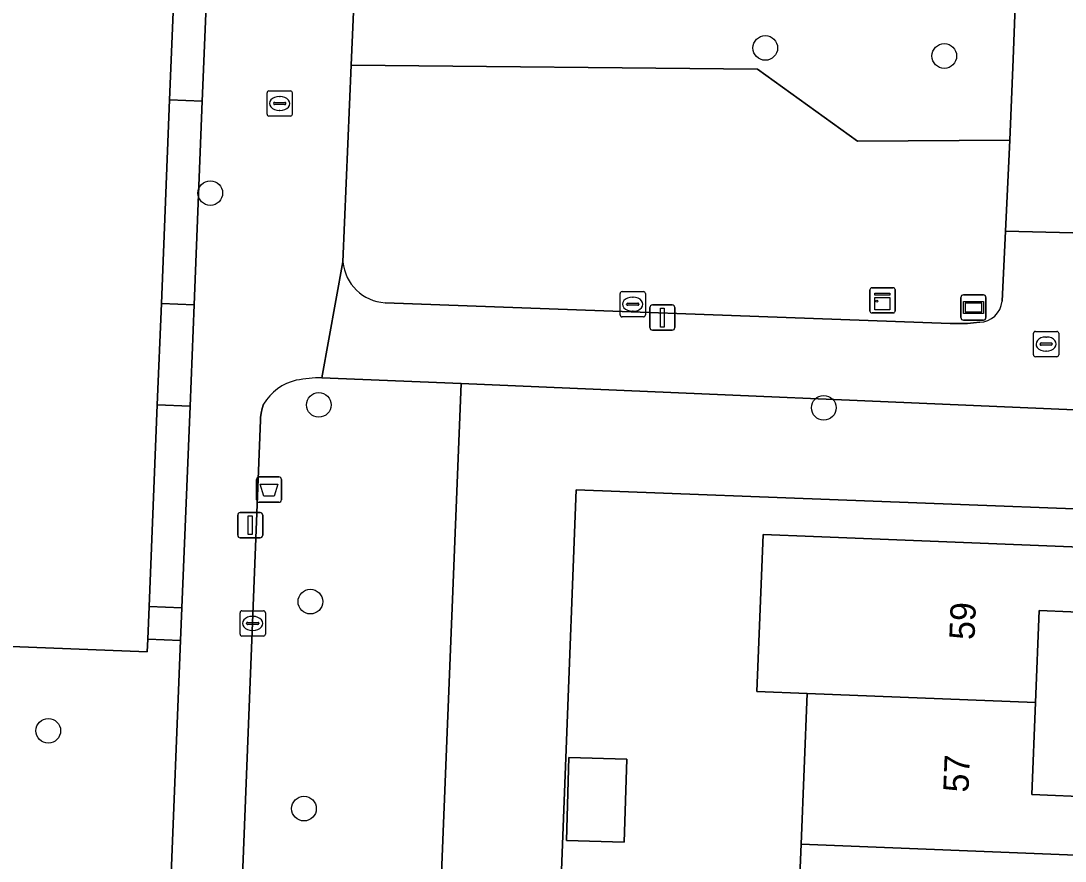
# Model space of a CAD drawing. Extents: x 160786 to 161429, y 386828 to 387485.
# Drawn here: x 161125.82 to 161167.19, y 387264.64 to 387297.93 of the extents above; entities that cross this region are included whole.
import ezdxf

# ---------------------------------------------------------------- set-up
doc = ezdxf.new("R2010")
doc.units = 0
for name, color, linetype in [('IMGEO_Afvalbak', 7, 'Continuous'), ('IMGEO_Boom', 7, 'Continuous'), ('IMGEO_Brandkraan', 7, 'Continuous'), ('IMGEO_Erf', 7, 'Continuous'), ('IMGEO_Groenvoorziening', 7, 'Continuous'), ('IMGEO_Haag', 7, 'Continuous'), ('IMGEO_Kast', 7, 'Continuous'), ('IMGEO_Kolk', 7, 'Continuous'), ('IMGEO_Lichtmast', 7, 'Continuous'), ('IMGEO_Pand', 7, 'Continuous'), ('IMGEO_Pand_nummerreeks', 7, 'Continuous'), ('IMGEO_Straatnaambord', 7, 'Continuous'), ('IMGEO_Voetpad_open', 7, 'Continuous')]:
    doc.layers.add(name, color=color, linetype=linetype)

msp = doc.modelspace()

# ---------------------------------------------------------------- linework, layer by layer
at = {"layer": 'IMGEO_Afvalbak'}
for p, q in [((161135.253, 387279.862), (161136.043, 387279.862)), ((161136.043, 387279.862), (161135.253, 387279.862)), ((161135.153, 387278.962), (161135.153, 387279.762)), ((161135.153, 387279.762), (161135.153, 387278.962)), ((161136.143, 387279.762), (161136.143, 387278.962)), ((161136.143, 387278.962), (161136.143, 387279.762)), ((161136.043, 387278.862), (161135.253, 387278.862)), ((161135.253, 387278.862), (161136.043, 387278.862))]:
    msp.add_line(p, q, dxfattribs=at)
msp.add_lwpolyline([(161135.296, 387279.576), (161136, 387279.576), (161135.851, 387279.106), (161135.445, 387279.106), (161135.296, 387279.576)], dxfattribs=at)
for centre, start, end in [((161135.253, 387279.762), 90, 180), ((161135.253, 387279.762), 90, 180), ((161136.043, 387279.762), 0, 90), ((161136.043, 387279.762), 360, 90), ((161135.253, 387278.962), 180, 270), ((161135.253, 387278.962), 180, 270), ((161136.043, 387278.962), 270, 0), ((161136.043, 387278.962), 270, 0)]:
    msp.add_arc(centre, 0.1, start, end, dxfattribs=at)
at = {"layer": 'IMGEO_Boom'}
for centre in [(161155.308, 387296.861), (161162.4, 387296.541), (161133.321, 387291.109), (161137.619, 387282.717), (161157.626, 387282.603), (161137.288, 387274.923), (161126.901, 387269.805), (161137.032, 387266.723)]:
    msp.add_circle(centre, 0.489, dxfattribs=at)
at = {"layer": 'IMGEO_Brandkraan'}
for p, q in [((161166.01, 387285.627), (161166.862, 387285.627)), ((161165.935, 387284.701), (161165.935, 387285.553)), ((161166.237, 387285.17), (161166.635, 387285.17)), ((161166.423, 387285.407), (161166.448, 387285.407)), ((161166.936, 387285.553), (161166.936, 387284.701)), ((161166.194, 387285.121), (161166.194, 387285.133)), ((161166.632, 387285.084), (161166.234, 387285.084)), ((161166.446, 387284.847), (161166.421, 387284.847)), ((161166.678, 387285.133), (161166.678, 387285.121)), ((161166.862, 387284.627), (161166.01, 387284.627))]:
    msp.add_line(p, q, dxfattribs=at)
for points in [[(161166.01, 387285.627), (161166.862, 387285.627)], [(161165.935, 387284.701), (161165.935, 387285.553)], [(161166.936, 387285.553), (161166.936, 387284.701)], [(161166.862, 387284.627), (161166.01, 387284.627)]]:
    msp.add_lwpolyline(points, dxfattribs=at)
for centre, radius, start, end in [((161166.012, 387285.551), 0.0765, 91.552, 178.448), ((161166.012, 387285.551), 0.0765, 91.552, 178.448), ((161166.86, 387285.551), 0.0765, 1.552, 88.448), ((161166.86, 387285.551), 0.0765, 1.552, 88.448), ((161166.234, 387285.13), 0.0403, 85.8775, 175.7526), ((161166.639, 387285.132), 0.0386, 1.7309, 96.639), ((161166.231, 387285.12), 0.0366, 178.938, 274.7102), ((161166.635, 387285.127), 0.043, 264.8664, 352.4533), ((161166.012, 387284.703), 0.0765, 181.552, 268.448), ((161166.012, 387284.703), 0.0765, 181.552, 268.448), ((161166.86, 387284.703), 0.0765, 271.552, 358.448), ((161166.86, 387284.703), 0.0765, 271.552, 358.448)]:
    msp.add_arc(centre, radius, start, end, dxfattribs=at)
for centre, major_axis, ratio, start_param, end_param in [((161166.422, 387285.127), (-0.387, 0.002), 0.722429, 4.712389, 7.853982), ((161166.447, 387285.127), (-0.39, 0.002), 0.717154, 1.570796, 4.712389)]:
    msp.add_ellipse(centre, major_axis=major_axis, ratio=ratio, start_param=start_param, end_param=end_param, dxfattribs=at)
at = {"layer": 'IMGEO_Erf'}
for points in [[(161118.71, 387273.409), (161130.826, 387272.934), (161130.846, 387273.44), (161130.898, 387274.729), (161131.22, 387282.723), (161131.382, 387286.74), (161131.706, 387294.803), (161131.872, 387298.919), (161132.197, 387307.013), (161132.363, 387311.119), (161132.69, 387319.253), (161132.836, 387322.88), (161133.163, 387331.014), (161133.328, 387335.1), (161133.655, 387343.234), (161133.705, 387344.483), (161133.977, 387351.235), (161125.69, 387351.675)], [(161156.486, 387259.313), (161156.726, 387265.307), (161156.965, 387271.285), (161154.974, 387271.365), (161155.223, 387277.582), (161157.214, 387277.502), (161168.771, 387277.039), (161168.668, 387274.465), (161166.166, 387274.565), (161166.02, 387270.922), (161165.874, 387267.279), (161168.363, 387267.179), (161168.27, 387264.845), (161168.177, 387262.51)]]:
    msp.add_lwpolyline(points, dxfattribs=at)
for points in [[(161169.695, 387236.621), (161169.709, 387236.985), (161170.226, 387250), (161171.292, 387276.874), (161171.353, 387278.449), (161147.813, 387279.35), (161146.59, 387247.494), (161144.751, 387247.564), (161143.809, 387246.052), (161142.905, 387223.679), (161145.53, 387223.573), (161145.284, 387217.483), (161143.51, 387217.555), (161143.326, 387213), (161145.236, 387212.923), (161144.626, 387197.819), (161152.342, 387197.507), (161162.811, 387197.084), (161168.116, 387196.87), (161168.129, 387197.191), (161168.175, 387198.326)], [(161147.429, 387265.462), (161147.528, 387268.745), (161149.818, 387268.675), (161149.719, 387265.392)]]:
    msp.add_lwpolyline(points, close=True, dxfattribs=at)
at = {"layer": 'IMGEO_Groenvoorziening'}
for points in [[(161165.127, 387296.415), (161165.215, 387298.514), (161160.443, 387298.696), (161151.391, 387299.041), (161143.553, 387299.341), (161139.046, 387299.512), (161138.908, 387296.177), (161155.006, 387296.014), (161158.958, 387293.171), (161164.993, 387293.208)], [(161133.005, 387294.751), (161131.706, 387294.803), (161131.382, 387286.74), (161132.681, 387286.688)], [(161132.519, 387282.671), (161131.22, 387282.723), (161130.898, 387274.729), (161132.198, 387274.677)]]:
    msp.add_lwpolyline(points, close=True, dxfattribs=at)
for points in [[(161164.829, 387289.6), (161164.993, 387293.208), (161158.958, 387293.171), (161155.006, 387296.014), (161138.908, 387296.177), (161138.578, 387288.383)], [(161164.69, 387286.821), (161164.829, 387289.6)], [(161140.247, 387286.767), (161162.637, 387285.947), (161163.314, 387285.947), (161163.563, 387285.964), (161163.803, 387285.99)], [(161143.258, 387283.56), (161137.745, 387283.796)], [(161169.71, 387282.428), (161143.258, 387283.56), (161141.91, 387250), (161139.825, 387198.117), (161139.779, 387196.96), (161145.215, 387196.742), (161162.77, 387196.036), (161162.811, 387197.084), (161152.342, 387197.507), (161144.626, 387197.819), (161145.236, 387212.923), (161143.326, 387213), (161143.51, 387217.555), (161145.284, 387217.483), (161145.53, 387223.573), (161142.905, 387223.679), (161143.809, 387246.052), (161144.751, 387247.564), (161146.59, 387247.494), (161147.813, 387279.35), (161171.353, 387278.449), (161171.423, 387280.284), (161171.366, 387280.761)], [(161141.91, 387250), (161143.258, 387283.56)], [(161135.431, 387282.75), (161135.375, 387282.575), (161135.335, 387282.396), (161135.31, 387282.213), (161135.304, 387282.111), (161134.046, 387250), (161131.872, 387194.508), (161131.578, 387188.533)], [(161132.146, 387273.388), (161130.846, 387273.44), (161130.826, 387272.934), (161118.71, 387273.409), (161109.694, 387273.762), (161104.756, 387273.893), (161104.419, 387265.337), (161104.372, 387264.144)], [(161131.733, 387263.132), (161132.146, 387273.388)]]:
    msp.add_lwpolyline(points, dxfattribs=at)
for centre, radius, start, end in [((161140.345, 387288.538), 1.774, 185.0156, 266.8331), ((161163.775, 387286.909), 0.92, 271.7735, 354.4926), ((161137.172, 387281.713), 2.027, 102.6102, 149.2292), ((161137.866, 387277.667), 6.13, 91.1319, 100.6804)]:
    msp.add_arc(centre, radius, start, end, dxfattribs=at)
at = {"layer": 'IMGEO_Haag'}
for points in [[(161133.005, 387294.751), (161131.706, 387294.803), (161131.382, 387286.74), (161132.681, 387286.688)], [(161132.519, 387282.671), (161131.22, 387282.723), (161130.898, 387274.729), (161132.198, 387274.677)]]:
    msp.add_lwpolyline(points, close=True, dxfattribs=at)
at = {"layer": 'IMGEO_Kast'}
for p, q in [((161159.454, 387286.435), (161159.454, 387287.276)), ((161159.454, 387287.276), (161159.454, 387286.435)), ((161159.529, 387287.36), (161160.37, 387287.36)), ((161160.37, 387287.36), (161159.529, 387287.36)), ((161160.454, 387287.285), (161160.454, 387286.444)), ((161160.454, 387286.444), (161160.454, 387287.285)), ((161160.379, 387286.36), (161159.538, 387286.36)), ((161159.538, 387286.36), (161160.379, 387286.36))]:
    msp.add_line(p, q, dxfattribs=at)
for points in [[(161159.649, 387287.15), (161160.249, 387287.15), (161160.249, 387287.065), (161159.649, 387287.065), (161159.649, 387287.15)], [(161159.649, 387286.975), (161160.249, 387286.975), (161160.249, 387286.486), (161159.649, 387286.486), (161159.649, 387286.975)]]:
    msp.add_lwpolyline(points, dxfattribs=at)
msp.add_circle((161159.733, 387286.824), 0.0377, dxfattribs=at)
for centre, start, end in [((161159.532, 387287.282), 92.4484, 184.2845), ((161159.532, 387287.282), 92.4484, 184.2845), ((161160.376, 387287.282), 2.4484, 94.2845), ((161160.376, 387287.282), 2.4484, 94.2845), ((161159.532, 387286.438), 182.4484, 274.2845), ((161159.532, 387286.438), 182.4484, 274.2845), ((161160.376, 387286.438), 272.4484, 4.2845), ((161160.376, 387286.438), 272.4484, 4.2845)]:
    msp.add_arc(centre, 0.0779, start, end, dxfattribs=at)
at = {"layer": 'IMGEO_Kolk'}
for p, q in [((161135.57, 387294.233), (161135.57, 387295.085)), ((161135.645, 387295.159), (161136.497, 387295.159)), ((161136.571, 387295.085), (161136.571, 387294.233)), ((161135.829, 387294.653), (161135.829, 387294.665)), ((161135.872, 387294.702), (161136.27, 387294.702)), ((161136.058, 387294.939), (161136.083, 387294.939)), ((161136.313, 387294.665), (161136.313, 387294.653)), ((161136.267, 387294.616), (161135.869, 387294.616)), ((161136.081, 387294.379), (161136.056, 387294.379)), ((161136.497, 387294.159), (161135.645, 387294.159)), ((161149.558, 387286.281), (161149.558, 387287.133)), ((161149.633, 387287.207), (161150.485, 387287.207)), ((161150.046, 387286.987), (161150.071, 387286.987)), ((161150.559, 387287.133), (161150.559, 387286.281)), ((161149.817, 387286.701), (161149.817, 387286.713)), ((161150.255, 387286.664), (161149.857, 387286.664)), ((161149.86, 387286.75), (161150.258, 387286.75)), ((161150.069, 387286.427), (161150.044, 387286.427)), ((161150.301, 387286.713), (161150.301, 387286.701)), ((161150.485, 387286.207), (161149.633, 387286.207)), ((161134.501, 387273.633), (161134.501, 387274.485)), ((161134.576, 387274.559), (161135.428, 387274.559)), ((161135.502, 387274.485), (161135.502, 387273.633)), ((161134.76, 387274.053), (161134.76, 387274.065)), ((161135.198, 387274.016), (161134.8, 387274.016)), ((161134.803, 387274.102), (161135.201, 387274.102)), ((161134.989, 387274.339), (161135.014, 387274.339)), ((161135.244, 387274.065), (161135.244, 387274.053)), ((161135.428, 387273.559), (161134.576, 387273.559)), ((161135.012, 387273.779), (161134.987, 387273.779))]:
    msp.add_line(p, q, dxfattribs=at)
for points in [[(161135.57, 387294.233), (161135.57, 387295.085)], [(161135.645, 387295.159), (161136.497, 387295.159)], [(161136.571, 387295.085), (161136.571, 387294.233)], [(161136.497, 387294.159), (161135.645, 387294.159)], [(161149.558, 387286.281), (161149.558, 387287.133)], [(161149.633, 387287.207), (161150.485, 387287.207)], [(161150.559, 387287.133), (161150.559, 387286.281)], [(161150.485, 387286.207), (161149.633, 387286.207)], [(161134.501, 387273.633), (161134.501, 387274.485)], [(161134.576, 387274.559), (161135.428, 387274.559)], [(161135.502, 387274.485), (161135.502, 387273.633)], [(161135.428, 387273.559), (161134.576, 387273.559)]]:
    msp.add_lwpolyline(points, dxfattribs=at)
for centre, radius, start, end in [((161135.647, 387295.083), 0.0765, 91.552, 178.448), ((161135.647, 387295.083), 0.0765, 91.552, 178.448), ((161136.495, 387295.083), 0.0765, 1.552, 88.448), ((161136.495, 387295.083), 0.0765, 1.552, 88.448), ((161135.869, 387294.662), 0.0403, 85.8775, 175.7526), ((161136.274, 387294.664), 0.0386, 1.7309, 96.639), ((161135.866, 387294.652), 0.0366, 178.938, 274.7102), ((161136.27, 387294.659), 0.043, 264.8664, 352.4533), ((161135.647, 387294.235), 0.0765, 181.552, 268.448), ((161135.647, 387294.235), 0.0765, 181.552, 268.448), ((161136.495, 387294.235), 0.0765, 271.552, 358.448), ((161136.495, 387294.235), 0.0765, 271.552, 358.448), ((161149.635, 387287.131), 0.0765, 91.552, 178.448), ((161149.635, 387287.131), 0.0765, 91.552, 178.448), ((161150.483, 387287.131), 0.0765, 1.552, 88.448), ((161150.483, 387287.131), 0.0765, 1.552, 88.448), ((161149.857, 387286.71), 0.0403, 85.8775, 175.7526), ((161149.854, 387286.7), 0.0366, 178.938, 274.7102), ((161150.258, 387286.707), 0.043, 264.8664, 352.4533), ((161150.262, 387286.712), 0.0386, 1.7309, 96.639), ((161149.635, 387286.283), 0.0765, 181.552, 268.448), ((161149.635, 387286.283), 0.0765, 181.552, 268.448), ((161150.483, 387286.283), 0.0765, 271.552, 358.448), ((161150.483, 387286.283), 0.0765, 271.552, 358.448), ((161134.578, 387274.483), 0.0765, 91.552, 178.448), ((161134.578, 387274.483), 0.0765, 91.552, 178.448), ((161135.426, 387274.483), 0.0765, 1.552, 88.448), ((161135.426, 387274.483), 0.0765, 1.552, 88.448), ((161134.8, 387274.062), 0.0403, 85.8775, 175.7526), ((161134.797, 387274.052), 0.0366, 178.938, 274.7102), ((161135.201, 387274.059), 0.043, 264.8664, 352.4533), ((161135.205, 387274.064), 0.0386, 1.7309, 96.639), ((161134.578, 387273.635), 0.0765, 181.552, 268.448), ((161134.578, 387273.635), 0.0765, 181.552, 268.448), ((161135.426, 387273.635), 0.0765, 271.552, 358.448), ((161135.426, 387273.635), 0.0765, 271.552, 358.448)]:
    msp.add_arc(centre, radius, start, end, dxfattribs=at)
for centre, major_axis, ratio, start_param, end_param in [((161136.057, 387294.659), (-0.387, 0.002), 0.722429, 4.712389, 7.853982), ((161136.082, 387294.659), (-0.39, 0.002), 0.717154, 1.570796, 4.712389), ((161150.045, 387286.707), (-0.387, 0.002), 0.722429, 4.712389, 7.853982), ((161150.07, 387286.707), (-0.39, 0.002), 0.717154, 1.570796, 4.712389), ((161134.988, 387274.059), (-0.387, 0.002), 0.722429, 4.712389, 7.853982), ((161135.013, 387274.059), (-0.39, 0.002), 0.717154, 1.570796, 4.712389)]:
    msp.add_ellipse(centre, major_axis=major_axis, ratio=ratio, start_param=start_param, end_param=end_param, dxfattribs=at)
at = {"layer": 'IMGEO_Lichtmast'}
for p, q in [((161150.735, 387285.778), (161150.735, 387286.578)), ((161150.735, 387286.578), (161150.735, 387285.778)), ((161150.835, 387286.678), (161151.625, 387286.678)), ((161151.625, 387286.678), (161150.835, 387286.678)), ((161151.725, 387286.578), (161151.725, 387285.778)), ((161151.725, 387285.778), (161151.725, 387286.578)), ((161151.625, 387285.678), (161150.835, 387285.678)), ((161150.835, 387285.678), (161151.625, 387285.678)), ((161134.406, 387277.552), (161134.406, 387278.352)), ((161134.406, 387278.352), (161134.406, 387277.552)), ((161134.506, 387278.452), (161135.296, 387278.452)), ((161135.296, 387278.452), (161134.506, 387278.452)), ((161135.396, 387278.352), (161135.396, 387277.552)), ((161135.396, 387277.552), (161135.396, 387278.352)), ((161135.296, 387277.452), (161134.506, 387277.452)), ((161134.506, 387277.452), (161135.296, 387277.452))]:
    msp.add_line(p, q, dxfattribs=at)
for points in [[(161151.155, 387286.553), (161151.305, 387286.553), (161151.305, 387285.803), (161151.155, 387285.803), (161151.155, 387286.553)], [(161134.826, 387278.327), (161134.976, 387278.327), (161134.976, 387277.577), (161134.826, 387277.577), (161134.826, 387278.327)]]:
    msp.add_lwpolyline(points, dxfattribs=at)
for centre, start, end in [((161150.835, 387286.578), 90, 180), ((161150.835, 387286.578), 90, 180), ((161151.625, 387286.578), 0, 90), ((161151.625, 387286.578), 360, 90), ((161150.835, 387285.778), 180, 270), ((161150.835, 387285.778), 180, 270), ((161151.625, 387285.778), 270, 0), ((161151.625, 387285.778), 270, 0), ((161134.506, 387278.352), 90, 180), ((161134.506, 387278.352), 90, 180), ((161135.296, 387278.352), 0, 90), ((161135.296, 387278.352), 360, 90), ((161134.506, 387277.552), 180, 270), ((161134.506, 387277.552), 180, 270), ((161135.296, 387277.552), 270, 0), ((161135.296, 387277.552), 270, 0)]:
    msp.add_arc(centre, 0.1, start, end, dxfattribs=at)
at = {"layer": 'IMGEO_Pand'}
for points in [[(161166.166, 387274.565), (161168.668, 387274.465), (161168.771, 387277.039), (161157.214, 387277.502), (161155.223, 387277.582), (161154.974, 387271.365), (161156.965, 387271.285), (161166.02, 387270.922)], [(161168.27, 387264.845), (161168.363, 387267.179), (161165.874, 387267.279), (161166.02, 387270.922), (161156.965, 387271.285), (161156.726, 387265.307)], [(161147.429, 387265.462), (161149.719, 387265.392), (161149.818, 387268.675), (161147.528, 387268.745)], [(161165.498, 387258.952), (161165.644, 387262.611), (161168.177, 387262.51), (161168.27, 387264.845), (161156.726, 387265.307), (161156.486, 387259.313)]]:
    msp.add_lwpolyline(points, close=True, dxfattribs=at)
at = {"layer": 'IMGEO_Straatnaambord'}
for p, q in [((161163.059, 387286.176), (161163.059, 387286.976)), ((161163.059, 387286.976), (161163.059, 387286.176)), ((161163.159, 387287.076), (161163.949, 387287.076)), ((161163.949, 387287.076), (161163.159, 387287.076)), ((161164.049, 387286.976), (161164.049, 387286.176)), ((161164.049, 387286.176), (161164.049, 387286.976)), ((161163.949, 387286.076), (161163.159, 387286.076)), ((161163.159, 387286.076), (161163.949, 387286.076))]:
    msp.add_line(p, q, dxfattribs=at)
for points in [[(161163.16, 387286.808), (161163.948, 387286.808), (161163.948, 387286.344), (161163.16, 387286.344), (161163.16, 387286.808)], [(161163.225, 387286.743), (161163.225, 387286.409), (161163.883, 387286.409), (161163.883, 387286.743), (161163.225, 387286.743)]]:
    msp.add_lwpolyline(points, dxfattribs=at)
for centre, start, end in [((161163.159, 387286.976), 90, 180), ((161163.159, 387286.976), 90, 180), ((161163.949, 387286.976), 0, 90), ((161163.949, 387286.976), 360, 90), ((161163.159, 387286.176), 180, 270), ((161163.159, 387286.176), 180, 270), ((161163.949, 387286.176), 270, 0), ((161163.949, 387286.176), 270, 0)]:
    msp.add_arc(centre, 0.1, start, end, dxfattribs=at)
at = {"layer": 'IMGEO_Voetpad_open'}
for points in [[(161137.745, 387283.796), (161138.578, 387288.383), (161138.908, 387296.177), (161139.046, 387299.512), (161142.214, 387375.996)], [(161168.933, 387313.767), (161169.022, 387316.036), (161168.124, 387316.072), (161168.195, 387317.88), (161169.093, 387317.844), (161169.235, 387321.452), (161168.337, 387321.488), (161168.419, 387323.586), (161169.317, 387323.55), (161169.459, 387327.157), (161168.561, 387327.193), (161168.632, 387329.002), (161169.53, 387328.966), (161169.672, 387332.573), (161168.774, 387332.609), (161168.845, 387334.418), (161169.743, 387334.382), (161169.832, 387336.641), (161166.813, 387336.716), (161165.215, 387298.514), (161165.127, 387296.415), (161164.993, 387293.208), (161164.829, 387289.6), (161170.163, 387289.466)], [(161134.627, 387335.048), (161134.462, 387330.962), (161134.135, 387322.828), (161133.989, 387319.201), (161133.662, 387311.067), (161133.497, 387306.961), (161133.171, 387298.867), (161133.005, 387294.751), (161132.681, 387286.688), (161132.519, 387282.671), (161132.198, 387274.677), (161132.146, 387273.388), (161131.733, 387263.132)], [(161247.486, 387286.367), (161204.081, 387288.161), (161170.163, 387289.466), (161164.829, 387289.6), (161164.69, 387286.821)], [(161138.578, 387288.383), (161137.745, 387283.796), (161143.258, 387283.56), (161169.71, 387282.428), (161181.145, 387282.379), (161181.317, 387282.373), (161201.652, 387281.657), (161201.851, 387281.648), (161211.164, 387281.363), (161211.335, 387281.354), (161231.449, 387280.529), (161245.64, 387279.689), (161245.804, 387283.807), (161258.09, 387283.318), (161270.377, 387282.829), (161270.534, 387287.689)], [(161163.803, 387285.99), (161163.563, 387285.964), (161163.314, 387285.947), (161162.637, 387285.947), (161140.247, 387286.767)], [(161135.375, 387282.575), (161135.431, 387282.75)], [(161131.578, 387188.533), (161131.872, 387194.508), (161134.046, 387250), (161135.304, 387282.111), (161135.31, 387282.213), (161135.335, 387282.396), (161135.375, 387282.575)]]:
    msp.add_lwpolyline(points, dxfattribs=at)
for points in [[(161133.171, 387298.867), (161131.872, 387298.919), (161131.706, 387294.803), (161133.005, 387294.751)], [(161132.681, 387286.688), (161131.382, 387286.74), (161131.22, 387282.723), (161132.519, 387282.671)], [(161132.198, 387274.677), (161130.898, 387274.729), (161130.846, 387273.44), (161132.146, 387273.388)]]:
    msp.add_lwpolyline(points, close=True, dxfattribs=at)
for centre, radius, start, end in [((161140.345, 387288.538), 1.774, 185.0156, 266.8331), ((161163.775, 387286.909), 0.92, 271.7735, 354.4926), ((161137.172, 387281.713), 2.027, 102.6102, 149.2292), ((161137.866, 387277.667), 6.13, 91.1319, 100.6804)]:
    msp.add_arc(centre, radius, start, end, dxfattribs=at)

# ---------------------------------------------------------------- texts
at = {"layer": 'IMGEO_Pand_nummerreeks'}
for s, rotation, p in [('59', 87.7198, (161163.597, 387273.392)), ('57', 87.7194, (161163.358, 387267.35))]:
    msp.add_text(s, height=1, rotation=rotation, dxfattribs=at).set_placement(p)

doc.saveas('drawing.dxf')
